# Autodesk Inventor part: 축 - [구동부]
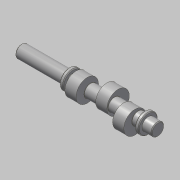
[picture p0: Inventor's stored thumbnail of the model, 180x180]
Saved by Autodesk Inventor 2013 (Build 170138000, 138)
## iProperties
Company: 한국ATC센터
Created: 2014-08
Part Number: 축 - [구동부]
Document SubType Name: Modeling
Designer: mdu
Density: 7.86 g/cm^3
Material: 강철, 연강
Mass: 516.584 g
Surface Area: 162.515 cm^2
Volume: 65.7231 cm^3
Author: mdu
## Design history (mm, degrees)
sketch "스케치1"
  geometry: L1 (-91.5, 0)-(91.5, 0); L2 (-91.5, 0)-(-91.5, 8.5); L3 (-91.5, 8.5)-(-27.5, 8.5); L4 (-27.5, 8.5)-(-27.5, 13); L5 (-27.5, 13)-(-22.5, 13); L6 (-22.5, 13)-(-22.5, 8.5); L7 (-22.5, 8.5)-(73.5, 8.5); L8 (73.5, 8.5)-(73.5, 13); L9 (73.5, 13)-(78.5, 13); L10 (78.5, 13)-(78.5, 8.5); L11 (78.5, 8.5)-(91.5, 8.5); L12 (91.5, 8.5)-(91.5, 0); 2 further points
  constraints: 24 end point, 5 parallel, 1 coincident, 1 horizontal, 1 midpoint, 1 perpendicular
  dimensions: "d0" = 183 distance of L1.start L1.end (derived); "d2" = 17 diameter of L3 L1; "d3" = 26 diameter of L5 L1; "d4" = 17 diameter of L7 L1; "d5" = 26 diameter of L9 L1; "d6" = 17 diameter of L11 L1; "d7" = 5 distance of L8.end L9.end; "d8" = 5 distance of L4.end L5.end; "d10" = 64 distance of L2.end L3.end; "d11" = 13 distance of L10.end L11.end; "d35" = 96 distance between parallel lines of L8 L6
revolve "회전1" sketch "스케치1" stored, may be unused: angle "d12" = 90 deg
node "작업 평면7"
sketch "스케치6"
  geometry: C1 r 15 at (0, 5); 1 further point
  constraints: 1 centre point, 1 vertical alignment
  dimensions: "d37" = 30 diameter of C1; "d38" = 5 distance of C1.centre point (0, 0)
extrude "돌출4" join sketch "스케치6" stored distance "d33" = 15; taper "d34" = 0 deg
node "작업 평면8"
sketch "스케치7"
  geometry: L1 (0, 0)-(-6.5, -11.258); L2 (0, 0)-(13, 0); C1 r 15 at (-2.5, -4.33); A1 r 13 centre (0, 0) between (-6.5, -11.258) and (13, 0) reference; 1 further point
  constraints: 4 end point, 2 point on circle, 1 centre point, 1 horizontal, 1 point on line
  dimensions: "d40" = 120 deg angle of L1 L2; "d41" = 30 diameter of C1; "d42" = 5 distance of point (0, 0) C1.centre
extrude "돌출5" join sketch "스케치7" stored distance "d43" = 15; taper "d44" = 0 deg
node "작업 평면9"
sketch "스케치8"
  geometry: L1 (0, 0)-(4.25, -7.361); L2 (0, 0)-(-8.5, 0); C1 r 15 at (2.5, -4.33); A1 r 8.5 centre (0, 0) between (4.25, -7.361) and (-8.5, 0) reference; 1 further point
  constraints: 4 end point, 2 point on circle, 1 centre point, 1 horizontal, 1 point on line
  dimensions: "d46" = 120 deg angle of L1 L2; "d47" = 30 diameter of C1; "d48" = 5 distance of point (0, 0) C1.centre
extrude "돌출6" join sketch "스케치8" stored distance "d49" = 15; taper "d50" = 0 deg
node "작업 평면3"
sketch "스케치5"
  geometry: L1 (32, 8.5)-(32, -8.5) reference; L2 (27.5, -2.5)-(14.5, -2.5); L3 (14.5, 2.5)-(27.5, 2.5); A1 r 2.5 centre (14.5, 0) between (14.5, 2.5) and (14.5, -2.5); A2 r 2.5 centre (27.5, 0) between (27.5, -2.5) and (27.5, 2.5); 4 further points
  constraints: 4 end point, 4 point on circle, 4 tangent, 2 centre point, 2 point on line, 1 horizontal alignment, 1 midpoint, 1 parallel, 1 perpendicular
  dimensions: "d23" = 5 distance between parallel lines of L3 L2; "d36" = 20 dimension on A1 L1; "d52" = 2 distance edge to line of A2 L1
extrude "돌출3" cut sketch "스케치5" distance "d25" = 3; taper "d26" = 0 deg
chamfer "모따기1" distance "d27" = 1; stored, may be unused: second distance "d28" = 2, angle "d29" = 45 deg
fillet "모깎기1" dims "d51" = 0.3
chamfer "모따기2" distance "d53" = 1; stored, may be unused: second distance "d54" = 2, angle "d55" = 45 deg
node "작업 평면10"
node "솔리드1"
other parameters: "d39" = -32, "d45" = 32
